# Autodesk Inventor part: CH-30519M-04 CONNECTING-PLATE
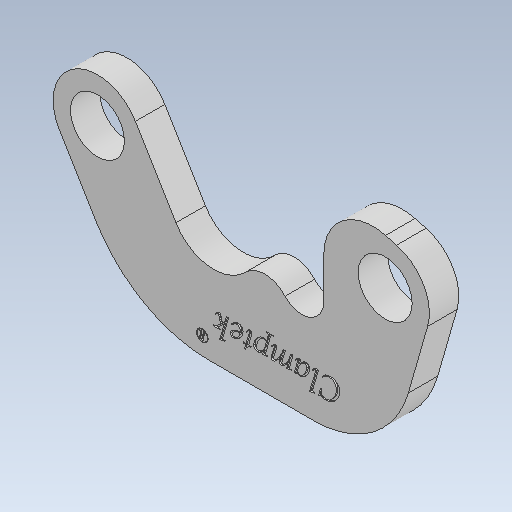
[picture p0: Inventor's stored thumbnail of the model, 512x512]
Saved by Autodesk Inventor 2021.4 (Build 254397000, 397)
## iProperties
Created: 2017-11
Part Number: CH-30519M-04 CONNECTING-PLATE
Material: Ogólny
Document SubType Name: Modeling
Designer: user
Density: 1 g/cm^3
Appearance: Domyślna
Author: user
Revision Number: ÈÎºÎ
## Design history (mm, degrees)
feature "À­Éì6"
node "Bryła1"
